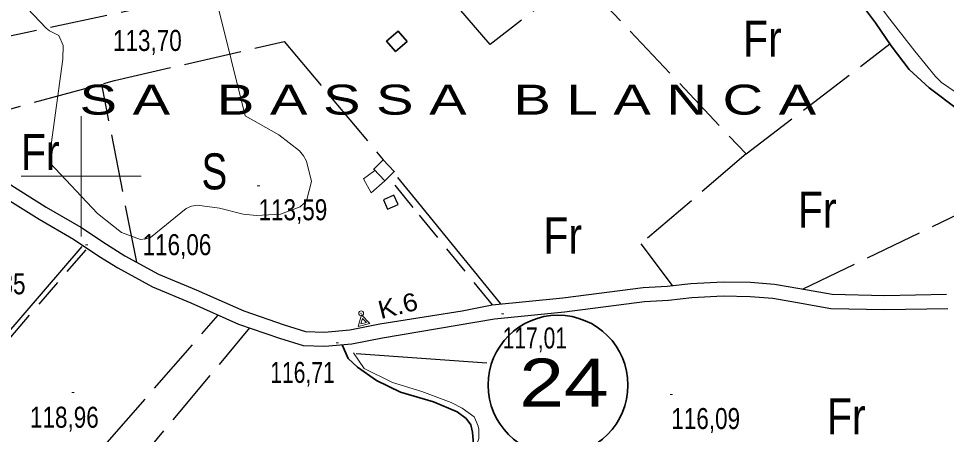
# Model space of a CAD drawing. Extents: x 483840 to 488445, y 4386047 to 4389027.
# Drawn here: x 485974 to 486360.3, y 4387392.5 to 4387565.7 of the extents above; entities that cross this region are included whole.
import ezdxf
from ezdxf.enums import TextEntityAlignment as Align

# ---------------------------------------------------------------- set-up
doc = ezdxf.new("R2010")
doc.units = 0
doc.header["$LTSCALE"] = 4
doc.header["$PDMODE"] = 32
doc.header["$PDSIZE"] = 2
doc.linetypes.add('LONG_DASHED', pattern=[7.5, 6, -1.5])
doc.linetypes.add('MEDIUM_DASHED', pattern=[4.5, 3, -1.5])
for name, color, linetype, lineweight in [('1', 7, 'Continuous', 13), ('13', 7, 'Continuous', 25), ('25', 7, 'LONG_DASHED', 25), ('36', 7, 'Continuous', 25), ('38', 7, 'Continuous', 25), ('41', 7, 'Continuous', 13), ('47', 7, 'Continuous', 35), ('48', 7, 'MEDIUM_DASHED', 25), ('51', 7, 'Continuous', 13), ('6', 7, 'Continuous', 35), ('7', 7, 'Continuous', 13), ('9', 7, 'Continuous', 13)]:
    doc.layers.add(name, color=color, linetype=linetype, lineweight=lineweight)
doc.layers.add('31', color=7, linetype='Continuous')
doc.layers.add('5', color=7, linetype='Continuous')

msp = doc.modelspace()

# ---------------------------------------------------------------- linework, layer by layer
at = {"layer": '1'}
for p, q in [((486000, 4387525), (486000, 4387475)), ((485975, 4387500), (486025, 4387500))]:
    msp.add_line(p, q, dxfattribs=at)
at = {"layer": '25'}
for p, q in [((486023.2, 4387464.22), (486008.6, 4387538.42)), ((486300.4, 4387453.07), (486400.26, 4387501.1)), ((485980.62, 4387329.59), (486070.3, 4387436.86))]:
    msp.add_line(p, q, dxfattribs=at)
for points in [[(486185.24, 4387683.01), (486149.48, 4387650.24), (486208.09, 4387582.24), (486276.9, 4387509.3), (486336.77, 4387555.11)], [(486207.1, 4387583.4), (486170.33, 4387554.87), (486109.26, 4387625.52)], [(486020.11, 4387607.45), (486080.72, 4387616.63), (486098.81, 4387585.68), (485944.62, 4387552.91)], [(485951.63, 4387522.98), (486013.89, 4387539.85), (486084.58, 4387556.17), (486125.82, 4387506.81)], [(486276.9, 4387509.3), (486233.07, 4387471.88), (486246.12, 4387454.49)], [(486026.94, 4387288.29), (486008.21, 4387300.94), (485999.28, 4387311.5), (485989.67, 4387321.47), (485981.98, 4387329.53), (485976.28, 4387329.76), (485971.46, 4387343.94), (486057.15, 4387442.22)]]:
    msp.add_lwpolyline(points, dxfattribs=at)
at = {"layer": '36'}
for points in [[(485962.71, 4387501.42), (485985.53, 4387487.21), (485999.97, 4387478.82), (486010.53, 4387471.69), (486018.26, 4387466.93), (486032.24, 4387459.24), (486047.97, 4387452.71), (486067.73, 4387443.96), (486084.52, 4387438.16), (486093.46, 4387435.34), (486101.37, 4387435.15), (486111.95, 4387436.05), (486124.36, 4387438.5), (486158.65, 4387443.94), (486171.22, 4387446.53), (486200.61, 4387449.41), (486233.99, 4387453.74), (486244.06, 4387454.27), (486253.83, 4387455.33), (486267.28, 4387456.04), (486278.77, 4387455.87), (486288.75, 4387455.13), (486299.24, 4387453.26), (486312.7, 4387450.89), (486334.51, 4387450.35), (486360.31, 4387450.88)], [(485959.53, 4387496.48), (485982.5, 4387482.18), (485996.85, 4387473.84), (486007.34, 4387466.75), (486015.3, 4387461.85), (486029.69, 4387453.94), (486045.65, 4387447.31), (486065.57, 4387438.48), (486082.67, 4387432.58), (486092.49, 4387429.48), (486101.55, 4387429.27), (486112.77, 4387430.22), (486125.48, 4387432.73), (486172.11, 4387440.71), (486201.27, 4387443.57), (486234.53, 4387447.88), (486244.53, 4387448.41), (486254.3, 4387449.47), (486267.39, 4387450.16), (486278.51, 4387450), (486288.02, 4387449.29), (486298.22, 4387447.47), (486312.11, 4387445.02), (486334.5, 4387444.47), (486360.89, 4387445.01)]]:
    msp.add_lwpolyline(points, dxfattribs=at)
at = {"layer": '38', "linetype": 'MEDIUM_DASHED'}
for points in [[(486171.24, 4387446.53), (486138.32, 4387486.98), (486129.62, 4387497.69)], [(486001.94, 4387469.43), (485961.08, 4387421.96)]]:
    msp.add_lwpolyline(points, dxfattribs=at)
at = {"layer": '38'}
for points in [[(486174.76, 4387446.88), (486140.61, 4387488.84), (486131.91, 4387499.55)], [(486000.36, 4387470.79), (485959.58, 4387423.41)]]:
    msp.add_lwpolyline(points, dxfattribs=at)
at = {"layer": '41'}
for p, q in [((486115.4, 4387437.47), (486116.77, 4387442.28)), ((486115.4, 4387437.47), (486120.25, 4387438.69)), ((486120.25, 4387438.69), (486116.77, 4387442.28))]:
    msp.add_line(p, q, dxfattribs=at)
msp.add_lwpolyline([(486117.14, 4387440.82), (486116.48, 4387438.52), (486118.81, 4387439.1)], close=True, dxfattribs=at)
msp.add_point((486116.61, 4387442.93), dxfattribs=at)
at = {"layer": '47'}
for points in [[(486135.75, 4387556.19), (486130.94, 4387551.97), (486127.2, 4387556.24), (486132.01, 4387560.46)], [(486125.82, 4387506.81), (486130.43, 4387501.99), (486126.44, 4387498.17), (486121.83, 4387502.99)]]:
    msp.add_lwpolyline(points, close=True, dxfattribs=at)
at = {"layer": '48'}
msp.add_lwpolyline([(486125.88, 4387490.15), (486127.64, 4387486.28), (486132, 4387488.26), (486130.24, 4387492.13)], close=True, dxfattribs=at)
at = {"layer": '51'}
for points in [[(486319.66, 4387592.12), (486319.83, 4387588.22), (486335.8, 4387566.68), (486347.07, 4387552.11), (486355.78, 4387541.56), (486358.29, 4387539.05), (486372.63, 4387529.16), (486387.78, 4387518.36), (486399.37, 4387510.32), (486408.77, 4387500.95), (486414.88, 4387492.61), (486420.2, 4387481.66), (486422.32, 4387472.32), (486423.49, 4387465.4)], [(486126.44, 4387498.17), (486120.82, 4387493.07), (486117.53, 4387498.97), (486122.34, 4387502.47)], [(486113.49, 4387426.47), (486117.89, 4387419.96), (486129.67, 4387414.16), (486141.92, 4387410.38), (486154.16, 4387405.78), (486158.7, 4387403.39), (486163.68, 4387399.87), (486164.77, 4387397.37), (486165.35, 4387396.01), (486165.56, 4387394.74), (486165.68, 4387393.01), (486165.57, 4387390.76), (486150.17, 4387347.38), (486150.05, 4387343.93), (486148.59, 4387341.55), (486145.15, 4387337.1), (486119.09, 4387299.35), (486098.08, 4387272.94)]]:
    msp.add_lwpolyline(points, dxfattribs=at)
at = {"layer": '6', "lineweight": 25}
msp.add_line((486114.54, 4387426.24), (486168.95, 4387422.36), dxfattribs=at)
at = {"layer": '6'}
for points in [[(486116.23, 4387792.4), (486132.03, 4387782.95), (486147.96, 4387771.75), (486163.27, 4387760.17), (486172.57, 4387751.14), (486183, 4387741), (486196.38, 4387726.7), (486211.2, 4387709.12), (486226.06, 4387689.1), (486244.26, 4387669.22), (486254.87, 4387655.62), (486266.52, 4387644.16), (486282.31, 4387626.78), (486304.74, 4387601.82), (486311.03, 4387591.7), (486319.95, 4387578.44), (486330.78, 4387563.95), (486337.26, 4387554.38), (486344.84, 4387544.52), (486353.11, 4387536.82), (486365.48, 4387527.49)], [(486108.72, 4387429.88), (486111.15, 4387424.2), (486115.09, 4387420.58), (486123.07, 4387414.99), (486132.97, 4387410.05), (486146.69, 4387406.04), (486156.54, 4387401.92), (486160.35, 4387399.14), (486162.24, 4387396.44), (486163.03, 4387393.52), (486163.22, 4387390.05), (486163.01, 4387387.04), (486162.1, 4387384.84), (486149.71, 4387347.62), (486147.02, 4387341.86), (486144.83, 4387338.28), (486141.42, 4387333.4), (486137.75, 4387328.8), (486123.51, 4387308.31), (486098.49, 4387275.55)]]:
    msp.add_lwpolyline(points, dxfattribs=at)
msp.add_circle((486198.6, 4387413.05), 29.1, dxfattribs=at)
at = {"layer": '7'}
for p, q in [((486073.39, 4387496.07), (486074.39, 4387496.07)), ((486001.8, 4387471.43), (486002.8, 4387471.43)), ((486175, 4387442.68), (486176, 4387442.68)), ((486106.25, 4387430.67), (486107.25, 4387430.67)), ((485996.15, 4387409.99), (485997.15, 4387409.99)), ((486245.25, 4387409.12), (486246.25, 4387409.12))]:
    msp.add_line(p, q, dxfattribs=at)
at = {"layer": '9'}
for points in [[(486046.02, 4387487.53), (486043.73, 4387486.65), (486028.97, 4387474.58), (486026.9, 4387473.95), (486024.79, 4387473.74), (486016.91, 4387476.57), (486006.8, 4387484.55), (485987.02, 4387505.55), (485987.2, 4387510.19), (485992.44, 4387548.78), (485992.51, 4387554.46), (485990.75, 4387558.63), (485986.86, 4387560.6), (485985.47, 4387561.74), (485969.89, 4387578.15)], [(486056.72, 4387572.13), (486068.38, 4387525.13), (486082.32, 4387517.25), (486090.95, 4387510.56), (486092.59, 4387508.5), (486093.92, 4387506.36), (486096.01, 4387497.88), (486094.03, 4387490.29), (486092.78, 4387488.7), (486091.22, 4387487.33), (486083.08, 4387484.25), (486073.01, 4387483.64), (486067.49, 4387484.2), (486057.63, 4387486.8), (486048.38, 4387488.03), (486046.02, 4387487.53)]]:
    msp.add_lwpolyline(points, dxfattribs=at)

# ---------------------------------------------------------------- texts
at = {"layer": '13', "width": 1.25}
msp.add_text('24', height=20, dxfattribs=at).set_placement((486201.05, 4387404.09), align=Align.CENTER)
at = {"layer": '31'}
for s, width, p in [('Fr', 0.85, (486283.68, 4387549.82)), ('Fr', 0.85, (485983.03, 4387502.63)), ('S', 0.8, (486055.51, 4387494.56)), ('Fr', 0.85, (486306.51, 4387478.6)), ('Fr', 0.85, (486200.54, 4387467.85)), ('Fr', 0.85, (486318.6, 4387392.6))]:
    msp.add_text(s, height=15, dxfattribs=dict(at, width=width)).set_placement(p, align=Align.CENTER)
at = {"layer": '41', "width": 1.1}
msp.add_text('K.6', height=7.5, rotation=14.044, dxfattribs=at).set_placement((486124.78, 4387440.53))
at = {"layer": '5', "width": 1.4}
msp.add_text('S A   B A S S A   B L A N C A', height=12.49, dxfattribs=at).set_placement((486306.06, 4387525.68), align=Align.RIGHT)
at = {"layer": '7'}
for s, width, p in [('113,70', 0.8, (486013.29, 4387552.2)), ('113,59', 0.8, (486073.89, 4387481.7)), ('116,06', 0.8, (486025.61, 4387467.16)), ('117,85', 0.8, (485948.26, 4387450.87)), ('117,01', 0.75, (486175.5, 4387428.31)), ('116,71', 0.75, (486078.78, 4387413.97)), ('118,96', 0.8, (485978.74, 4387395.3)), ('116,09', 0.8, (486245.75, 4387394.75))]:
    msp.add_text(s, height=8.75, dxfattribs=dict(at, width=width)).set_placement(p)

doc.saveas('drawing.dxf')
